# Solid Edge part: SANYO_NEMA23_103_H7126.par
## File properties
Subject: SANYO_NEMA23_103_H7126
Author: f_grande
Template: Normal.par
Last saved by: f_grande
Revision: 3
Application: Solid Edge
Material: Acciaio
Stile della faccia: Acciaio
Stile di riempimento: ANSI32(Acciaio)
Stile virtuale: Acciaio lavorato a macchina
Coef. of Thermal Exp: 0.0
Thermal Conductivity: 32.0
Specific Heat: 481.0
Modulus of Elasticity: 199947953000.0
Poisson's Ratio: 0.29
Yield Stress: 262000766.0
Ultimate Stress: 358527364.0
Elongation: 0.0
Tipo di contenuto documento: 0
Densità: 7833,000 kg/m^3
Precisione: 0,990
Document Number: KR0151
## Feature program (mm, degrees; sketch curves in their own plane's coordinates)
sketch for "unnamed Protrusion 1" plane through (0, 0, 0) normal (0, -1, 0) x-axis (1, 0, 0)
  line (-28.5, 28.5) -> (28.5, 28.5)
  line (28.5, 28.5) -> (28.5, -28.5)
  line (28.5, -28.5) -> (-28.5, -28.5)
  line (-28.5, -28.5) -> (-28.5, 28.5)
  dimension (linear) = 28.5
  dimension (linear) = 28.5
extrude "unnamed Protrusion 1" add finite 75.8 along -normal
sketch for "Foro_1" plane through (0, 75.8, 0) normal (0, 1, 0) x-axis (-1, 0, 0)
  hole centre (23.57, 23.57) bore radius 2.25
hole "Foro_1" diameter 4.5 through
sketch for "unnamed Hole 1" plane through (0, 75.8, 0) normal (0, 1, 0) x-axis (-1, 0, 0)
  hole centre (23.57, -23.57) bore radius 2.25
hole "unnamed Hole 1" through
sketch for "unnamed Hole 2" plane through (0, 75.8, 0) normal (0, 1, 0) x-axis (-1, 0, 0)
  hole centre (-23.57, -23.57) bore radius 2.25
hole "unnamed Hole 2" through
sketch for "unnamed Hole 3" plane through (0, 75.8, 0) normal (0, 1, 0) x-axis (-1, 0, 0)
  hole centre (-23.57, 23.57) bore radius 2.25
hole "unnamed Hole 3" through
pattern "unnamed Pattern 1" of "Foro_1", "unnamed Hole 1", "unnamed Hole 2", "unnamed Hole 3"
fillet "Rotondo_1" radius 5
sketch for "ExtrudedCutout_1" #1 plane through (0, 75.8, 0) normal (0, 1, 0) x-axis (-1, 0, 0)
  line (-28.5, -19.5) -> (-19.5, -19.5)
  line (-19.5, -19.5) -> (-19.5, -28.5)
  line (-19.5, -28.5) -> (-28.5, -28.5)
  line (-28.5, -28.5) -> (-28.5, -19.5)
sketch for "ExtrudedCutout_1" #2 plane through (0, 75.8, 0) normal (0, 1, 0) x-axis (-1, 0, 0)
  line (19.5, -19.5) -> (28.5, -19.5)
  line (28.5, -19.5) -> (28.5, -28.5)
  line (28.5, -28.5) -> (19.5, -28.5)
  line (19.5, -28.5) -> (19.5, -19.5)
sketch for "ExtrudedCutout_1" #3 plane through (0, 75.8, 0) normal (0, 1, 0) x-axis (-1, 0, 0)
  line (19.5, 28.5) -> (19.5, 19.5)
  line (19.5, 19.5) -> (28.5, 19.5)
  line (28.5, 19.5) -> (28.5, 28.5)
  line (28.5, 28.5) -> (19.5, 28.5)
sketch for "ExtrudedCutout_1" #4 plane through (0, 75.8, 0) normal (0, 1, 0) x-axis (-1, 0, 0)
  line (-28.5, 28.5) -> (-19.5, 28.5)
  line (-19.5, 28.5) -> (-19.5, 19.5)
  line (-19.5, 19.5) -> (-28.5, 19.5)
  line (-28.5, 19.5) -> (-28.5, 28.5)
  dimension (linear) = 28.5
  dimension (linear) = 28.5
  dimension (linear) = 28.5
  dimension (linear) = 28.5
  dimension (linear) = 19.5
  dimension (linear) = 19.5
  dimension (linear) = 19.5
  dimension (linear) = 28.5
  dimension (linear) = 28.5
extrude "ExtrudedCutout_1" cut finite 70.8 along -normal
fillet "Rotondo_2" radius 5
fillet "Rotondo_3" radius 3
sketch for "ExtrudedProtrusion_2" plane through (0, 0, 0) normal (0, -1, 0) x-axis (-1, 0, 0)
  circle centre (0, 0) radius 21
extrude "ExtrudedProtrusion_2" add finite 1.5 along +normal
sketch for "ExtrudedProtrusion_3" plane through (0, -1.5, 0) normal (0, -1, 0) x-axis (-1, 0, 0)
  circle centre (0, 0) radius 3.175
extrude "ExtrudedProtrusion_3" add finite 20.6 along +normal
sketch for "ExtrudedCutout_3" #1 plane through (0, -1.5, 0) normal (0, -1, 0) x-axis (-1, 0, 0)
  circle centre (0, 0) radius 3.175
sketch for "ExtrudedCutout_3" #2 plane through (0, -1.5, 0) normal (0, -1, 0) x-axis (-1, 0, 0)
  circle centre (0, 0) radius 3.7966
extrude "ExtrudedCutout_3" cut finite 1.5 along -normal
sketch for "ExtrudedProtrusion_4" plane through (0, 75.8, 0) normal (0, 1, 0) x-axis (1, 0, 0)
  circle centre (0, 0) radius 3.175
extrude "ExtrudedProtrusion_4" add finite 15.5 along +normal
sketch for "ExtrudedCutout_4" #1 plane through (0, 75.8, 0) normal (0, 1, 0) x-axis (1, 0, 0)
  line (-1, 12.4175) -> (-1, 14.6315)
  arc centre (-2, 14.6315) radius 1 from (-1, 14.6315) to (-2.1354, 15.6223) ccw
  arc centre (0, 0) radius 15.7676 from (-12.5566, -9.5367) to (-2.1354, 15.6223) cw
  arc centre (-11.7603, -8.9318) radius 1 from (-12.5566, -9.5367) to (-11.0532, -9.639) ccw
  line (-9.4876, -8.0734) -> (-11.0532, -9.639)
  arc centre (-10.1947, -7.3663) radius 1 from (-9.4876, -8.0734) to (-9.3842, -6.7806) ccw
  arc centre (-2, 12.4175) radius 1 from (-1.841, 11.4303) to (-1, 12.4175) ccw
sketch for "ExtrudedCutout_4" #2 plane through (0, 75.8, 0) normal (0, 1, 0) x-axis (1, 0, 0)
  line (1, 12.4175) -> (1, 14.6315)
  arc centre (2, 14.6315) radius 1 from (2.1354, 15.6223) to (1, 14.6315) ccw
  arc centre (11.7603, -8.9318) radius 1 from (11.0532, -9.639) to (12.5566, -9.5367) ccw
  line (11.0532, -9.639) -> (9.4876, -8.0734)
  arc centre (10.1947, -7.3663) radius 1 from (9.3842, -6.7806) to (9.4876, -8.0734) ccw
  arc centre (0, 0) radius 11.5776 from (1.841, 11.4303) to (9.3842, -6.7806) cw
  arc centre (2, 12.4175) radius 1 from (1, 12.4175) to (1.841, 11.4303) ccw
sketch for "ExtrudedCutout_4" #3 plane through (0, 75.8, 0) normal (0, 1, 0) x-axis (1, 0, 0)
  line (9.639, -11.0532) -> (8.0734, -9.4876)
  arc centre (7.3663, -10.1947) radius 1 from (8.0734, -9.4876) to (6.7806, -9.3842) ccw
  arc centre (0, 0) radius 11.5776 from (6.7806, -9.3842) to (-6.7806, -9.3842) cw
  arc centre (-7.3663, -10.1947) radius 1 from (-6.7806, -9.3842) to (-8.0734, -9.4876) ccw
  line (-8.0734, -9.4876) -> (-9.639, -11.0532)
  arc centre (-8.9318, -11.7603) radius 1 from (-9.639, -11.0532) to (-9.5367, -12.5566) ccw
  arc centre (0, 0) radius 15.7676 from (9.5367, -12.5566) to (-9.5367, -12.5566) cw
  arc centre (8.9318, -11.7603) radius 1 from (9.5367, -12.5566) to (9.639, -11.0532) ccw
extrude "ExtrudedCutout_4" cut finite 2 along -normal
sketch for "ExtrudedProtrusion_5" plane through (0, 37.9, -28.5) normal (0, 0, -1) x-axis (1, 0, 0)
  line (-13, -26.9) -> (13, -26.9)
  line (13, -26.9) -> (13, -34.9)
  line (13, -34.9) -> (-13, -34.9)
  line (-13, -34.9) -> (-13, -26.9)
  dimension (linear) = 13
  dimension (linear) = 13
  dimension (linear) = 13
extrude "ExtrudedProtrusion_5" add finite 10 along +normal
sketch for "unnamed Cutout 1" #1 plane through (0, 72.8, -33.5) normal (0, 1, 0) x-axis (1, 0, 0)
  line (13, 5) -> (10.5, 5)
  line (10.5, 5) -> (10.5, 1)
  line (10.5, 1) -> (13, 1)
  line (13, 1) -> (13, 5)
sketch for "unnamed Cutout 1" #2 plane through (0, 72.8, -33.5) normal (0, 1, 0) x-axis (1, 0, 0)
  line (-13, 5) -> (-10.5, 5)
  line (-10.5, 5) -> (-10.5, 1)
  line (-10.5, 1) -> (-13, 1)
  line (-13, 1) -> (-13, 5)
  dimension (linear) = 13
  dimension (linear) = 13
  dimension (linear) = 13
  dimension (linear) = 13
extrude "unnamed Cutout 1" cut to key point along -normal
sketch for "ExtrudedProtrusion_6" #1 plane through (0, 68.8, -38.5) normal (0, 0, -1) x-axis (1, 0, 0)
  circle centre (-5.4, 0) radius 1
sketch for "ExtrudedProtrusion_6" #2 plane through (0, 68.8, -38.5) normal (0, 0, -1) x-axis (1, 0, 0)
  circle centre (-1.8, 0) radius 1
sketch for "ExtrudedProtrusion_6" #3 plane through (0, 68.8, -38.5) normal (0, 0, -1) x-axis (1, 0, 0)
  circle centre (1.8, 0) radius 1
sketch for "ExtrudedProtrusion_6" #4 plane through (0, 68.8, -38.5) normal (0, 0, -1) x-axis (1, 0, 0)
  circle centre (5.4, 0) radius 1
sketch for "ExtrudedProtrusion_6" #5 plane through (0, 68.8, -38.5) normal (0, 0, -1) x-axis (1, 0, 0)
  circle centre (9, 0) radius 1
sketch for "ExtrudedProtrusion_6" #6 plane through (0, 68.8, -38.5) normal (0, 0, -1) x-axis (1, 0, 0)
  circle centre (-9, 0) radius 1
extrude "ExtrudedProtrusion_6" add finite 8.2213 along +normal
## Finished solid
Body 1: solid body, 94 faces, 220 edges, 128 vertices.
  Faces by surface: cylinder 48, plane 46
  Edges by curve: line 124, circle 96
Bounding box of the edges (mm): 57.000 x 113.400 x 75.221, from (-28.5, -22.1, -46.7213) to (28.5, 91.3, 28.5).
Cylindrical faces by radius (mm): R1 x18, R2.25 x4, R3 x8, R3.175 x2, R3.7966 x1, R5 x8, R11.5776 x3, R15.7676 x3, R21 x1
Planar faces by outward normal: +x 6, +y 10, +z 3, -x 6, -y 5, -z 12, oblique 4
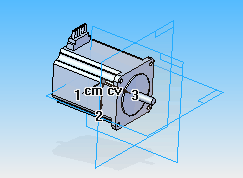
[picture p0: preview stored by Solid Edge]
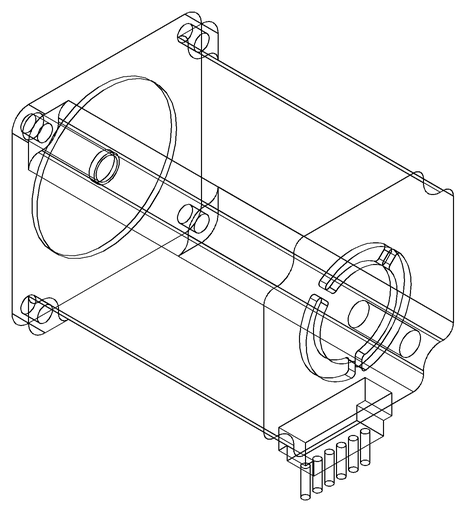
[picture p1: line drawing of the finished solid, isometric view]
